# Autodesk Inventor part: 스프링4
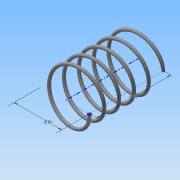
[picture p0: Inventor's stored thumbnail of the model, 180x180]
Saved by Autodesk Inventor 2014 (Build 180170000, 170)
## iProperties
Created: 2015-06
Part Number: 스프링4
Material: 강철, 연강
Document SubType Name: Modeling
Designer: MYHOME
Density: 1 g/cm^3
Appearance: 강철
Author: MYHOME
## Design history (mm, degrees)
sketch "스케치1"
  geometry: L1 (0, 0)-(8, 0); L2 (8, 0)-(8, 14.5); L3 (8, 14.5)-(0, 14.5); L4 (0, 14.5)-(0, 0); C1 r 0.5 at (8, 0)
  constraints: 8 end point, 2 parallel, 1 centre point, 1 coincident, 1 horizontal, 1 perpendicular
  dimensions: "d0" = 16 diameter of L2 L4; "d1" = 14.5 distance of L1.end L2.end (derived); "d2" = 1 diameter of C1
feature "코일2" sketch "스케치1" pitch "d17" = 10; turns "d19" = 5; dims "d18" = 14.5 (= d1), "d20" = 0, angle "d21" = 90 deg, angle "d22" = 90 deg, "d23" = 0, "d24" = 0
node "작업 평면3"
sketch "스케치4"
  geometry: L1 (-8.5, 0)-(-7.5, 0) reference; 1 further point
  constraints: 1 horizontal alignment
extrude "돌출3" cut sketch "스케치4" stored distance "d26" = 10; taper "d27" = 0 deg
node "작업 평면4"
sketch "스케치5"
  geometry: L1 (-7.5, 0)-(-8.5, 0) reference; 1 further point
  constraints: 1 horizontal alignment
extrude "돌출4" cut sketch "스케치5" stored distance "d29" = 10; taper "d30" = 0 deg
node "솔리드2"
node "절단 모서리 투영3"
node "절단 모서리 투영4"
other parameters: "d25" = 0, "d28" = 14.5 (= d1)
